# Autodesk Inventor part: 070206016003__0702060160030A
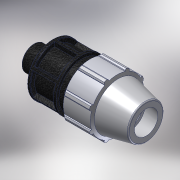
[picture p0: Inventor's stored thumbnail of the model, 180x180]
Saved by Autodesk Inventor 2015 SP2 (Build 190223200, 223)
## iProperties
Created: 2017-02
Part Number: 070206016003__0702060160030A
Material: PVC-Piping
Description: PLASSON MALE ADAPTOR 16-3/8"
Document SubType Name: Modeling
Designer: KIM
Mass: 92.6774 g
Surface Area: 199.44 cm^2
Volume: 66.1981 cm^3
Density: 1.4 g/cm^3
Appearance: PTFE
Author: KIM
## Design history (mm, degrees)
derived "07020.ipt"
feature "Solid1::07020.ipt"
tag "TaggingFeature1"
body "Solid1"
other parameters: "d2" = 16, "d4" = 10.85714, "d5" = 19, "d7" = 39, "d8" = 29.25, "d9" = 10.85714, "d11" = 2.17143, "d12" = 31.2, "d13" = 120 deg, "d14" = 24, "d15" = 12 deg, "d16" = 35.1, "d18" = 0.8, "d19" = 35 deg, "d20" = 17.5 deg, "d21" = 36.27, "d23" = 0, "d25" = 360 deg, "d27" = 0.78, "d34" = 1.95, "d36" = 0, "d42" = 19, "d43" = 1.17, "d46" = 0.48, "d49" = 59, "d51" = 76, "d52" = 13, "d53" = 0.32, "d55" = 360 deg, "d57" = 16.662, "d58" = 11.6634, "d59" = 15.2, "d_" = 16, "E_" = 39, "H_" = 76, "l_" = 59, "l_2" = 13, "R_" = 16.662
